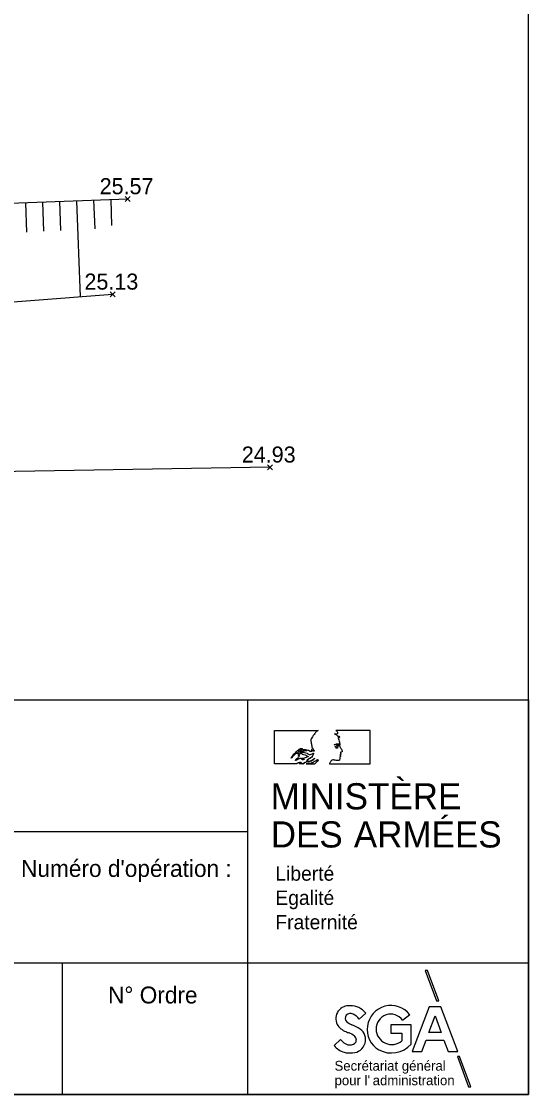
# Model space of a CAD drawing. Extents: x 37864 to 38032, y 453991 to 454052.
# Drawn here: x 37937.08 to 37946.06, y 453990.82 to 454009.85 of the extents above; entities that cross this region are included whole.
import ezdxf

# ---------------------------------------------------------------- set-up
doc = ezdxf.new("R2010")
doc.units = 0
for name, color, linetype in [('DH_CALCUL SURFACE-TEXTE', 7, 'Continuous'), ('DH_HACHURE-MOTIF', 7, 'Continuous'), ('GO_POTEAU', 7, 'Continuous'), ('PS_Dim', 7, 'Continuous')]:
    doc.layers.add(name, color=color, linetype=linetype)

# ---------------------------------------------------------------- blocks, each defined once
blk = doc.blocks.new('POINT_DISPLAY')
for p, q in [((-0.04375, -0.04375), (0.04375, 0.04375)), ((-0.04375, 0.04375), (0.04375, -0.04375))]:
    blk.add_line(p, q)
blk = doc.blocks.new('POINTCOT')
blk.add_blockref('POINT_DISPLAY', (0, 0))

msp = doc.modelspace()

# ---------------------------------------------------------------- linework, layer by layer
at = {"layer": 'DEFPOINTS'}
for p, q in [((37941.08, 453997.816), (37941.08, 453990.816)), ((37941.563, 453997.271), (37942.333, 453997.271)), ((37941.563, 453996.679), (37941.563, 453997.271)), ((37943.259, 453997.271), (37942.651, 453997.271)), ((37943.259, 453996.679), (37943.259, 453997.271)), ((37941.952, 453996.679), (37941.563, 453996.679)), ((37942.072, 453996.679), (37942.003, 453996.679)), ((37942.121, 453996.679), (37942.279, 453996.679)), ((37942.534, 453996.679), (37943.259, 453996.679)), ((37931.232, 453995.483), (37941.08, 453995.483)), ((37931.232, 453993.149), (37946.064, 453993.149)), ((37937.797, 453993.149), (37937.797, 453990.816)), ((37944.234, 453993.018), (37944.433, 453992.48)), ((37944.273, 453993.018), (37944.234, 453993.018)), ((37944.472, 453992.48), (37944.273, 453993.018)), ((37944.433, 453992.48), (37944.472, 453992.48)), ((37943.061, 453992.155), (37943.179, 453992.262)), ((37943.833, 453992.135), (37943.961, 453992.233)), ((37942.733, 453991.793), (37942.616, 453991.684)), ((37944.842, 453991.489), (37944.803, 453991.489)), ((37944.803, 453991.489), (37945.002, 453990.951)), ((37945.041, 453990.951), (37944.842, 453991.489)), ((37945.002, 453990.951), (37945.041, 453990.951))]:
    msp.add_line(p, q, dxfattribs=at)
for points in [[(37864.064, 453990.816), (37946.064, 453990.816), (37946.064, 454048.216), (37864.064, 454048.216)], [(37906.064, 453997.816), (37946.064, 453997.816), (37946.064, 453990.816), (37906.064, 453990.816)], [(37941.959, 453996.874), (37941.951, 453996.869), (37941.929, 453996.852), (37941.908, 453996.834), (37941.889, 453996.814), (37941.871, 453996.794), (37941.861, 453996.782), (37941.859, 453996.782), (37941.859, 453996.783), (37941.859, 453996.785), (37941.868, 453996.798), (37941.881, 453996.818), (37941.893, 453996.838), (37941.898, 453996.851), (37941.901, 453996.855), (37941.905, 453996.857), (37941.917, 453996.865), (37941.932, 453996.878), (37941.951, 453996.898), (37941.969, 453996.916), (37941.984, 453996.929), (37941.998, 453996.94), (37942.013, 453996.949), (37942.024, 453996.952), (37942.034, 453996.953), (37942.042, 453996.952), (37942.049, 453996.95), (37942.05, 453996.949), (37942.047, 453996.946), (37942.044, 453996.944), (37942.037, 453996.943), (37942.035, 453996.94), (37942.033, 453996.94), (37942.031, 453996.942), (37942.032, 453996.945), (37942.026, 453996.94), (37942.012, 453996.929), (37941.999, 453996.918), (37941.992, 453996.909), (37941.986, 453996.897), (37941.979, 453996.884), (37941.974, 453996.879), (37941.969, 453996.875), (37941.966, 453996.874), (37941.968, 453996.873), (37941.967, 453996.87), (37941.964, 453996.865), (37941.961, 453996.861), (37941.958, 453996.86), (37941.956, 453996.86), (37941.955, 453996.862), (37941.956, 453996.865), (37941.959, 453996.869), (37941.962, 453996.872), (37941.959, 453996.872)], [(37942.051, 453996.752), (37942.051, 453996.755), (37942.053, 453996.758), (37942.057, 453996.76), (37942.063, 453996.761), (37942.068, 453996.764), (37942.072, 453996.766), (37942.075, 453996.767), (37942.077, 453996.765), (37942.078, 453996.763), (37942.082, 453996.762), (37942.085, 453996.761), (37942.085, 453996.759), (37942.082, 453996.757), (37942.077, 453996.755), (37942.07, 453996.754), (37942.063, 453996.754), (37942.058, 453996.752), (37942.054, 453996.751)], [(37944.809, 453991.578), (37944.512, 453992.372), (37944.301, 453992.372), (37944.004, 453991.578), (37944.174, 453991.578), (37944.248, 453991.781), (37944.565, 453991.781), (37944.639, 453991.578)], [(37944.407, 453992.214), (37944.514, 453991.919), (37944.299, 453991.919)]]:
    msp.add_lwpolyline(points, close=True, dxfattribs=at)
for points in [[(37942.297, 453997.249), (37942.289, 453997.239), (37942.28, 453997.227), (37942.273, 453997.215), (37942.27, 453997.207), (37942.268, 453997.202), (37942.267, 453997.2), (37942.263, 453997.197), (37942.257, 453997.192), (37942.248, 453997.182), (37942.239, 453997.17), (37942.232, 453997.157), (37942.221, 453997.139), (37942.213, 453997.125), (37942.208, 453997.111), (37942.205, 453997.101), (37942.205, 453997.093), (37942.207, 453997.082), (37942.209, 453997.065), (37942.212, 453997.05), (37942.217, 453997.029), (37942.22, 453997.011), (37942.222, 453997.004), (37942.224, 453996.997), (37942.224, 453996.991), (37942.224, 453996.984), (37942.225, 453996.979), (37942.228, 453996.973), (37942.229, 453996.97), (37942.23, 453996.967), (37942.233, 453996.965), (37942.232, 453996.962), (37942.233, 453996.959), (37942.235, 453996.957), (37942.237, 453996.957), (37942.237, 453996.952), (37942.238, 453996.95), (37942.247, 453996.939), (37942.255, 453996.929), (37942.264, 453996.917), (37942.267, 453996.911), (37942.267, 453996.908), (37942.265, 453996.906), (37942.259, 453996.906), (37942.252, 453996.907), (37942.244, 453996.911), (37942.237, 453996.916), (37942.231, 453996.921), (37942.221, 453996.932), (37942.217, 453996.936), (37942.216, 453996.936), (37942.215, 453996.935), (37942.215, 453996.933), (37942.219, 453996.929), (37942.227, 453996.92), (37942.231, 453996.915), (37942.232, 453996.91), (37942.231, 453996.907), (37942.228, 453996.905), (37942.225, 453996.904), (37942.22, 453996.906), (37942.216, 453996.906), (37942.213, 453996.905), (37942.212, 453996.902), (37942.212, 453996.896)], [(37942.333, 453997.271), (37942.326, 453997.267), (37942.316, 453997.262), (37942.305, 453997.255), (37942.297, 453997.249)], [(37942.651, 453997.271), (37942.661, 453997.264), (37942.672, 453997.254), (37942.678, 453997.245), (37942.68, 453997.241), (37942.68, 453997.235), (37942.679, 453997.23), (37942.677, 453997.226), (37942.676, 453997.22), (37942.673, 453997.214), (37942.67, 453997.211), (37942.663, 453997.209), (37942.652, 453997.208), (37942.638, 453997.209), (37942.626, 453997.211), (37942.637, 453997.206), (37942.647, 453997.202), (37942.66, 453997.193), (37942.67, 453997.183), (37942.677, 453997.175), (37942.679, 453997.172), (37942.684, 453997.171), (37942.688, 453997.171), (37942.69, 453997.169), (37942.69, 453997.167), (37942.688, 453997.165), (37942.686, 453997.164), (37942.685, 453997.161), (37942.686, 453997.159), (37942.687, 453997.159), (37942.69, 453997.159), (37942.692, 453997.16), (37942.694, 453997.163), (37942.696, 453997.168), (37942.699, 453997.171), (37942.701, 453997.172), (37942.706, 453997.17), (37942.709, 453997.166), (37942.711, 453997.16), (37942.711, 453997.154), (37942.707, 453997.148), (37942.7, 453997.142), (37942.694, 453997.137), (37942.692, 453997.134), (37942.692, 453997.131), (37942.693, 453997.128), (37942.696, 453997.124), (37942.702, 453997.105), (37942.709, 453997.083), (37942.714, 453997.062), (37942.716, 453997.051), (37942.719, 453997.033), (37942.718, 453997.016), (37942.716, 453997.005), (37942.715, 453996.998), (37942.717, 453996.992), (37942.718, 453996.985), (37942.723, 453996.976)], [(37942.053, 453996.776), (37942.045, 453996.772), (37942.035, 453996.771), (37942.031, 453996.773), (37942.031, 453996.775), (37942.037, 453996.776), (37942.024, 453996.776), (37942.024, 453996.779), (37942.016, 453996.777), (37942.005, 453996.774), (37941.998, 453996.772), (37941.989, 453996.766), (37941.98, 453996.763), (37941.971, 453996.759), (37941.962, 453996.754), (37941.95, 453996.746), (37941.942, 453996.741), (37941.934, 453996.739), (37941.933, 453996.74), (37941.933, 453996.743), (37941.94, 453996.747), (37941.943, 453996.751), (37941.942, 453996.753), (37941.941, 453996.755), (37941.946, 453996.761), (37941.959, 453996.773), (37941.974, 453996.784), (37941.979, 453996.789), (37941.979, 453996.793), (37941.989, 453996.802), (37941.992, 453996.808), (37941.994, 453996.813), (37942, 453996.818), (37942.005, 453996.82), (37942.002, 453996.821), (37942.001, 453996.824), (37941.996, 453996.822), (37941.99, 453996.822), (37941.987, 453996.824), (37941.985, 453996.826), (37941.987, 453996.827), (37941.99, 453996.83), (37941.993, 453996.83), (37941.99, 453996.832), (37941.991, 453996.834), (37941.993, 453996.837), (37941.999, 453996.839), (37942.006, 453996.84), (37942.011, 453996.843), (37942.013, 453996.845), (37942.003, 453996.843), (37941.992, 453996.844), (37941.987, 453996.846), (37941.984, 453996.847), (37941.985, 453996.85), (37941.989, 453996.858), (37941.997, 453996.871), (37942.005, 453996.879), (37942.011, 453996.884), (37942.017, 453996.887), (37942.019, 453996.887), (37942.021, 453996.885), (37942.02, 453996.881), (37942.018, 453996.876), (37942.014, 453996.873)], [(37942.212, 453996.896), (37942.207, 453996.898), (37942.202, 453996.9), (37942.194, 453996.9), (37942.188, 453996.901), (37942.185, 453996.905), (37942.182, 453996.909), (37942.179, 453996.912), (37942.175, 453996.914), (37942.169, 453996.915), (37942.155, 453996.919), (37942.136, 453996.922), (37942.109, 453996.926), (37942.081, 453996.928), (37942.066, 453996.927), (37942.055, 453996.926), (37942.043, 453996.922), (37942.033, 453996.916), (37942.025, 453996.91), (37942.015, 453996.9), (37942.01, 453996.894), (37942.008, 453996.891), (37942.009, 453996.889), (37942.01, 453996.888), (37942.012, 453996.888), (37942.016, 453996.89), (37942.022, 453996.894), (37942.029, 453996.898), (37942.041, 453996.901), (37942.058, 453996.907), (37942.073, 453996.91), (37942.091, 453996.914), (37942.105, 453996.917), (37942.122, 453996.918), (37942.135, 453996.917), (37942.126, 453996.916), (37942.114, 453996.915), (37942.101, 453996.912), (37942.083, 453996.907), (37942.068, 453996.902), (37942.054, 453996.899), (37942.041, 453996.896), (37942.031, 453996.893), (37942.025, 453996.89)], [(37942.014, 453996.873), (37942.011, 453996.872), (37942.019, 453996.871), (37942.027, 453996.869), (37942.035, 453996.867), (37942.04, 453996.865), (37942.041, 453996.863), (37942.038, 453996.861), (37942.044, 453996.86), (37942.053, 453996.859), (37942.057, 453996.856), (37942.056, 453996.854), (37942.052, 453996.854), (37942.076, 453996.847), (37942.106, 453996.838), (37942.129, 453996.828), (37942.148, 453996.817), (37942.157, 453996.811), (37942.161, 453996.807), (37942.161, 453996.806), (37942.149, 453996.802), (37942.125, 453996.792), (37942.088, 453996.782), (37942.07, 453996.778), (37942.062, 453996.78), (37942.061, 453996.776), (37942.053, 453996.776)], [(37942.025, 453996.89), (37942.041, 453996.89), (37942.068, 453996.888), (37942.094, 453996.884), (37942.118, 453996.877), (37942.141, 453996.868), (37942.155, 453996.86), (37942.162, 453996.854), (37942.167, 453996.849), (37942.176, 453996.845), (37942.185, 453996.845)], [(37942.185, 453996.845), (37942.191, 453996.846), (37942.198, 453996.847), (37942.209, 453996.85), (37942.231, 453996.858), (37942.24, 453996.863), (37942.248, 453996.869), (37942.25, 453996.872), (37942.253, 453996.87), (37942.252, 453996.865), (37942.25, 453996.857), (37942.248, 453996.85), (37942.245, 453996.843), (37942.242, 453996.839), (37942.241, 453996.835), (37942.242, 453996.833), (37942.244, 453996.83), (37942.247, 453996.83), (37942.249, 453996.83), (37942.247, 453996.828), (37942.242, 453996.828), (37942.236, 453996.825), (37942.232, 453996.822), (37942.232, 453996.821), (37942.233, 453996.82), (37942.236, 453996.82), (37942.235, 453996.819), (37942.232, 453996.818), (37942.229, 453996.817), (37942.228, 453996.814), (37942.228, 453996.809), (37942.225, 453996.808), (37942.221, 453996.806), (37942.221, 453996.804), (37942.223, 453996.803), (37942.225, 453996.803), (37942.23, 453996.804), (37942.234, 453996.806), (37942.232, 453996.804), (37942.222, 453996.799), (37942.21, 453996.794), (37942.2, 453996.789), (37942.197, 453996.788), (37942.193, 453996.787), (37942.192, 453996.785), (37942.192, 453996.783), (37942.195, 453996.783), (37942.198, 453996.784), (37942.202, 453996.785), (37942.201, 453996.784), (37942.194, 453996.779), (37942.175, 453996.769), (37942.147, 453996.753), (37942.144, 453996.75), (37942.144, 453996.748), (37942.143, 453996.747), (37942.141, 453996.747), (37942.138, 453996.747), (37942.137, 453996.744), (37942.135, 453996.741), (37942.135, 453996.739), (37942.137, 453996.737), (37942.141, 453996.738), (37942.144, 453996.74), (37942.149, 453996.741)], [(37942.723, 453996.976), (37942.73, 453996.963), (37942.738, 453996.953), (37942.747, 453996.939), (37942.756, 453996.925), (37942.762, 453996.913), (37942.763, 453996.906), (37942.761, 453996.899), (37942.759, 453996.894), (37942.754, 453996.891), (37942.745, 453996.889), (37942.738, 453996.886), (37942.733, 453996.884), (37942.731, 453996.881), (37942.73, 453996.877), (37942.73, 453996.872), (37942.733, 453996.866), (37942.736, 453996.861), (37942.738, 453996.854), (37942.737, 453996.849), (37942.733, 453996.844), (37942.726, 453996.839), (37942.721, 453996.837), (37942.719, 453996.836), (37942.719, 453996.835), (37942.723, 453996.833), (37942.727, 453996.832), (37942.729, 453996.831), (37942.729, 453996.828), (37942.731, 453996.825), (37942.733, 453996.82), (37942.733, 453996.815), (37942.731, 453996.811), (37942.726, 453996.807), (37942.721, 453996.803), (37942.718, 453996.798), (37942.717, 453996.795), (37942.718, 453996.792), (37942.72, 453996.788), (37942.722, 453996.781), (37942.722, 453996.774), (37942.719, 453996.763), (37942.716, 453996.754), (37942.712, 453996.748), (37942.701, 453996.741), (37942.69, 453996.738), (37942.68, 453996.737), (37942.674, 453996.737), (37942.669, 453996.739), (37942.666, 453996.74), (37942.661, 453996.741), (37942.652, 453996.742), (37942.637, 453996.745), (37942.621, 453996.748), (37942.606, 453996.75), (37942.595, 453996.75), (37942.585, 453996.747), (37942.577, 453996.744), (37942.57, 453996.738), (37942.562, 453996.729), (37942.552, 453996.716), (37942.546, 453996.707), (37942.542, 453996.698), (37942.537, 453996.686), (37942.534, 453996.679)], [(37942.619, 453997.016), (37942.633, 453997.025), (37942.648, 453997.031), (37942.659, 453997.034), (37942.67, 453997.036), (37942.678, 453997.038), (37942.683, 453997.037), (37942.689, 453997.035), (37942.698, 453997.033), (37942.702, 453997.031), (37942.703, 453997.028), (37942.703, 453997.021), (37942.699, 453997.015), (37942.694, 453997.01), (37942.691, 453997.008), (37942.691, 453997.006), (37942.693, 453997.004), (37942.695, 453997.002), (37942.694, 453996.999), (37942.691, 453996.997), (37942.688, 453996.997), (37942.684, 453996.994), (37942.68, 453996.99), (37942.681, 453996.987), (37942.681, 453996.982), (37942.68, 453996.977), (37942.68, 453996.97), (37942.68, 453996.965), (37942.677, 453996.961), (37942.67, 453996.96), (37942.661, 453996.959), (37942.652, 453996.961), (37942.647, 453996.963), (37942.654, 453996.963), (37942.66, 453996.964), (37942.662, 453996.966), (37942.663, 453996.97), (37942.663, 453996.972), (37942.66, 453996.974), (37942.658, 453996.971), (37942.656, 453996.974), (37942.655, 453996.976), (37942.651, 453996.977), (37942.645, 453996.978), (37942.638, 453996.98), (37942.635, 453996.984), (37942.635, 453996.986), (37942.639, 453996.987), (37942.643, 453996.987), (37942.646, 453996.986), (37942.648, 453996.988), (37942.649, 453996.992), (37942.651, 453996.995), (37942.653, 453996.996), (37942.656, 453996.996), (37942.658, 453996.998), (37942.66, 453997), (37942.667, 453997.005), (37942.674, 453997.009), (37942.68, 453997.015), (37942.682, 453997.02), (37942.681, 453997.022), (37942.676, 453997.024), (37942.664, 453997.025), (37942.654, 453997.025)], [(37942.654, 453997.025), (37942.643, 453997.023), (37942.631, 453997.02), (37942.619, 453997.016)], [(37942.003, 453996.679), (37942.006, 453996.682), (37942.016, 453996.688), (37942.026, 453996.695), (37942.036, 453996.7), (37942.037, 453996.701), (37942.035, 453996.703), (37942.032, 453996.703), (37942.028, 453996.704), (37942.024, 453996.703), (37942.02, 453996.703), (37942.015, 453996.704), (37942.011, 453996.705), (37942.007, 453996.705), (37942.003, 453996.703), (37941.998, 453996.701), (37941.992, 453996.699), (37941.983, 453996.697), (37941.975, 453996.694), (37941.967, 453996.691), (37941.96, 453996.688), (37941.955, 453996.683), (37941.952, 453996.679)], [(37942.149, 453996.741), (37942.152, 453996.74), (37942.153, 453996.739), (37942.152, 453996.738), (37942.147, 453996.737), (37942.146, 453996.736), (37942.145, 453996.735), (37942.141, 453996.735), (37942.138, 453996.732), (37942.136, 453996.73), (37942.136, 453996.728), (37942.135, 453996.727), (37942.133, 453996.727), (37942.13, 453996.726), (37942.129, 453996.725), (37942.131, 453996.724), (37942.134, 453996.725), (37942.138, 453996.725), (37942.147, 453996.726), (37942.171, 453996.728), (37942.184, 453996.73), (37942.197, 453996.733), (37942.211, 453996.738), (37942.224, 453996.746), (37942.239, 453996.756), (37942.252, 453996.765), (37942.263, 453996.776), (37942.269, 453996.782), (37942.271, 453996.784), (37942.273, 453996.783), (37942.273, 453996.781), (37942.271, 453996.776), (37942.267, 453996.768), (37942.261, 453996.76), (37942.253, 453996.752), (37942.243, 453996.746), (37942.233, 453996.738), (37942.223, 453996.731), (37942.216, 453996.728), (37942.207, 453996.725), (37942.19, 453996.721), (37942.168, 453996.717), (37942.142, 453996.714), (37942.125, 453996.71), (37942.111, 453996.706), (37942.101, 453996.702), (37942.09, 453996.697), (37942.081, 453996.692), (37942.077, 453996.689), (37942.075, 453996.687), (37942.073, 453996.687), (37942.072, 453996.687), (37942.07, 453996.687), (37942.066, 453996.684), (37942.063, 453996.682), (37942.064, 453996.68), (37942.066, 453996.679), (37942.069, 453996.68), (37942.072, 453996.683), (37942.078, 453996.686), (37942.087, 453996.69), (37942.094, 453996.692), (37942.087, 453996.688), (37942.078, 453996.683), (37942.072, 453996.679)], [(37942.279, 453996.679), (37942.283, 453996.684), (37942.293, 453996.696), (37942.311, 453996.715), (37942.324, 453996.728), (37942.336, 453996.737), (37942.339, 453996.741), (37942.339, 453996.744), (37942.338, 453996.743), (37942.335, 453996.741), (37942.33, 453996.738), (37942.326, 453996.734), (37942.323, 453996.732), (37942.321, 453996.732), (37942.32, 453996.733), (37942.32, 453996.735), (37942.323, 453996.736), (37942.332, 453996.744), (37942.337, 453996.747), (37942.333, 453996.746), (37942.333, 453996.747), (37942.332, 453996.749), (37942.33, 453996.749), (37942.325, 453996.749), (37942.319, 453996.747), (37942.308, 453996.743), (37942.301, 453996.737), (37942.294, 453996.731), (37942.291, 453996.728), (37942.288, 453996.728), (37942.285, 453996.729), (37942.282, 453996.729), (37942.272, 453996.723), (37942.261, 453996.716), (37942.25, 453996.708), (37942.238, 453996.7), (37942.232, 453996.697), (37942.232, 453996.699), (37942.227, 453996.698), (37942.222, 453996.696), (37942.212, 453996.691), (37942.203, 453996.689), (37942.194, 453996.689), (37942.174, 453996.689), (37942.165, 453996.688), (37942.154, 453996.686), (37942.142, 453996.683), (37942.121, 453996.679)], [(37943.982, 453991.71), (37943.982, 453992.053), (37943.623, 453992.053), (37943.623, 453991.905), (37943.821, 453991.905), (37943.821, 453991.77)]]:
    msp.add_lwpolyline(points, dxfattribs=at)
for centre, radius, start, end in [((37942.882, 453992.161), 0.234, 144.1987, 205.9594), ((37942.889, 453992.143), 0.249, 86.0104, 141.5681), ((37942.908, 453992.043), 0.348, 38.7989, 90.3107), ((37943.628, 453991.972), 0.423, 38, 239.1837), ((37942.894, 453992.17), 0.0806, 139.5578, 228.1206), ((37942.906, 453992.152), 0.102, 62.0259, 136.6599), ((37942.998, 453992.267), 0.223, 224.6353, 253.3725), ((37942.846, 453992.003), 0.263, 35.1811, 65.6046), ((37943.622, 453991.983), 0.259, 35.7277, 182.0849), ((37942.928, 453992.209), 0.296, 210.4008, 249.6927), ((37943.104, 453992.531), 0.661, 245.0513, 250.5103), ((37942.494, 453991.051), 1.095, 57.5939, 66.2786), ((37942.949, 453991.791), 0.227, 343.0107, 54.4277), ((37943.639, 453991.979), 0.277, 181.1083, 310.8878), ((37942.945, 453991.949), 0.263, 216.582, 251.897), ((37942.898, 453991.843), 0.148, 256.1236, 307.2747), ((37942.757, 453991.578), 0.353, 51.5524, 68.988), ((37942.934, 453991.798), 0.244, 272.6923, 342.4014), ((37942.93, 453991.787), 0.0819, 358.7093, 55.2832), ((37942.941, 453991.778), 0.0704, 310.8873, 5.5663), ((37942.911, 453991.932), 0.385, 219.9839, 252.525), ((37942.902, 453992.04), 0.487, 257.2793, 275.0071), ((37943.633, 453992.019), 0.466, 241.584, 318.4992)]:
    msp.add_arc(centre, radius, start, end, dxfattribs=at)
at = {"layer": 'DH_HACHURE-MOTIF'}
for p, q in [((37937.146, 454006.631), (37937.165, 454006.11)), ((37937.448, 454006.642), (37937.467, 454006.125)), ((37937.751, 454006.653), (37937.769, 454006.139)), ((37938.053, 454006.664), (37938.115, 454004.963)), ((37938.355, 454006.676), (37938.374, 454006.169)), ((37938.658, 454006.687), (37938.674, 454006.226))]:
    msp.add_line(p, q, dxfattribs=at)
for points in [[(37906.194, 454005.424), (37911.405, 454006.387), (37916.68, 454006.683), (37923.362, 454007.241), (37929.423, 454007.054), (37934.123, 454006.52), (37938.96, 454006.698)], [(37906.194, 454005.424), (37911.469, 454005.161), (37923.405, 454004.731), (37929.021, 454004.355), (37934.479, 454004.687), (37938.691, 454005.007)]]:
    msp.add_lwpolyline(points, dxfattribs=at)
at = {"layer": 'PS_Dim'}
msp.add_lwpolyline([(37941.48, 454001.939), (37936.614, 454001.859), (37931.557, 454001.855), (37926.585, 454001.773), (37921.641, 454001.708), (37916.353, 454001.64), (37911.614, 454001.622), (37906.648, 454001.592), (37904.746, 454001.604)], dxfattribs=at)

# ---------------------------------------------------------------- block references
at = {"layer": 'DH_CALCUL SURFACE-TEXTE', "rotation": 2.2526485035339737e-05}
for p in [(37938.96, 454006.698), (37938.691, 454005.007), (37941.48, 454001.939)]:
    msp.add_blockref('POINTCOT', p, dxfattribs=at)

# ---------------------------------------------------------------- texts
at = {"layer": 'DEFPOINTS'}
for s, height, p in [('MINISTÈRE', 0.4641, (37941.494, 453995.873)), ('ARMÉES', 0.4641, (37942.967, 453995.197)), ('DES', 0.4641, (37941.494, 453995.197)), ("Numéro d'opération :", 0.3, (37937.069, 453994.675)), ('Liberté', 0.2553, (37941.577, 453994.608)), ('Egalité', 0.2553, (37941.577, 453994.178)), ('Fraternité', 0.2553, (37941.577, 453993.746)), ('N° Ordre', 0.3, (37938.61, 453992.431)), ('Secrétariat général', 0.17444, (37942.625, 453991.239)), ("pour l'", 0.1744, (37942.626, 453990.981)), ('administration', 0.17444, (37943.302, 453990.981))]:
    msp.add_text(s, height=height, rotation=360, dxfattribs=at).set_placement(p)
at = {"layer": 'GO_POTEAU'}
for s, p in [('25.57', (37938.462, 454006.782)), ('25.13', (37938.193, 454005.09)), ('24.93', (37940.982, 454002.023))]:
    msp.add_text(s, height=0.285, rotation=0, dxfattribs=at).set_placement(p)

doc.saveas('drawing.dxf')
